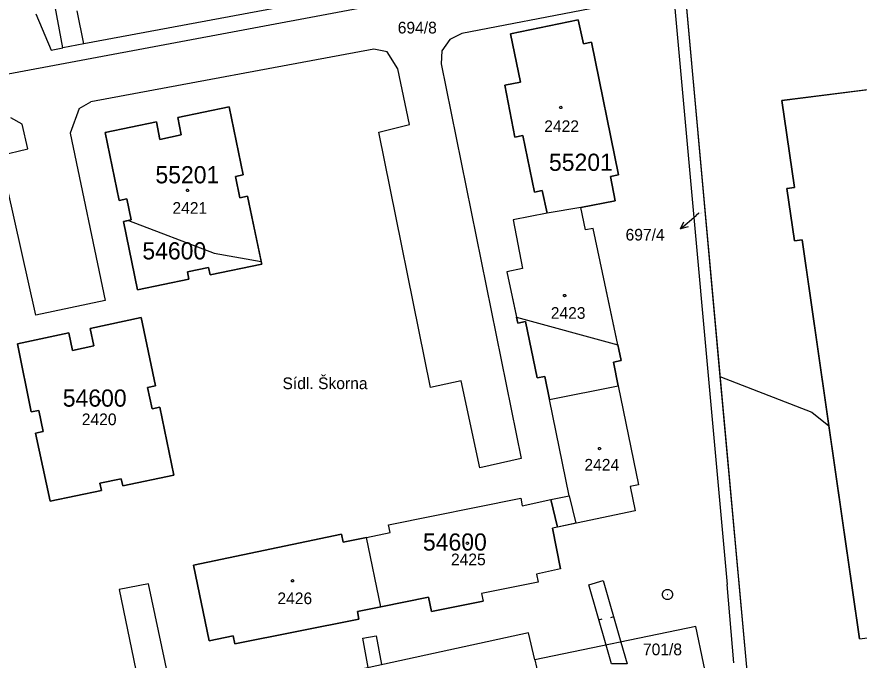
# Model space of a CAD drawing. Extents: x -777309 to -774195, y -1144706 to -1143600.
# Drawn here: x -775028.7 to -774906.1, y -1144612.1 to -1144518.5 of the extents above; entities that cross this region are included whole.
import ezdxf

# ---------------------------------------------------------------- set-up
doc = ezdxf.new("R2010")
doc.units = 0
for name, color, linetype in [('1', 7, 'Continuous'), ('11', 7, 'Continuous'), ('12', 7, 'Continuous'), ('13', 7, 'Continuous'), ('2', 7, 'Continuous'), ('5', 7, 'Continuous'), ('7', 7, 'Continuous'), ('8', 7, 'Continuous')]:
    doc.layers.add(name, color=color, linetype=linetype)

msp = doc.modelspace()

# ---------------------------------------------------------------- linework, layer by layer
at = {"layer": '1'}
for p, q in [((-774936.18, -1144481.83), (-774925.33, -1144601.09)), ((-775022.07, -1144523.02), (-775026.8, -1144497.32)), ((-774932.82, -1144500), (-774922.58, -1144612.56)), ((-775042.26, -1144529.08), (-774944.46, -1144510.75)), ((-774966.48, -1144512.63), (-775018.98, -1144522.44)), ((-775025.96, -1144518.08), (-775023.75, -1144523.35)), ((-775018.98, -1144522.44), (-775019.94, -1144517.62)), ((-774945.27, -1144517.35), (-774963.95, -1144520.9)), ((-774956.89, -1144520.97), (-774947, -1144518.92)), ((-774947, -1144518.92), (-774946.23, -1144522.42)), ((-774963.95, -1144520.9), (-774965.7, -1144521.8)), ((-774955.41, -1144527.99), (-774956.89, -1144520.97)), ((-774965.7, -1144521.8), (-774966.86, -1144523.45)), ((-774946.23, -1144522.42), (-774945.1, -1144522.18)), ((-774945.1, -1144522.18), (-774941.17, -1144541.48)), ((-775023.75, -1144523.35), (-775022.07, -1144523.02)), ((-775018.98, -1144522.44), (-775022.07, -1144523.02)), ((-774976.76, -1144523.19), (-775017.95, -1144530.88)), ((-774974.85, -1144523.59), (-774976.76, -1144523.19)), ((-774973.29, -1144526.08), (-774974.85, -1144523.59)), ((-774966.86, -1144523.45), (-774966.99, -1144525.35)), ((-774917.36, -1144530.66), (-774863.86, -1144523.96)), ((-774966.99, -1144525.35), (-774955.31, -1144582.77)), ((-774971.56, -1144534.16), (-774973.29, -1144526.08)), ((-774957.72, -1144528.45), (-774955.41, -1144527.99)), ((-774956.22, -1144536), (-774957.72, -1144528.45)), ((-774915.53, -1144543.32), (-774917.36, -1144530.66)), ((-775019.67, -1144531.82), (-775021, -1144535.42)), ((-775019.67, -1144531.82), (-775017.95, -1144530.88)), ((-774997.84, -1144531.6), (-775005.32, -1144533.13)), ((-774995.79, -1144541.5), (-774997.84, -1144531.6)), ((-775027.98, -1144534.13), (-775029.64, -1144533.2)), ((-775005.32, -1144533.13), (-775004.8, -1144535.68)), ((-775027.15, -1144537.72), (-775027.98, -1144534.13)), ((-775008.43, -1144533.77), (-775015.89, -1144535.3)), ((-775007.91, -1144536.32), (-775008.43, -1144533.77)), ((-774976.03, -1144535.26), (-774971.56, -1144534.16)), ((-775021, -1144535.42), (-775015.89, -1144559.74)), ((-775015.89, -1144535.3), (-775013.86, -1144545.2)), ((-775004.8, -1144535.68), (-775007.91, -1144536.32)), ((-774968.53, -1144572.4), (-774976.03, -1144535.26)), ((-774955.08, -1144535.77), (-774956.22, -1144536)), ((-774953.37, -1144543.99), (-774955.08, -1144535.77)), ((-775031.16, -1144538.67), (-775027.15, -1144537.72)), ((-775025.99, -1144561.88), (-775031.16, -1144538.67)), ((-774996.91, -1144541.74), (-774995.79, -1144541.5)), ((-774996.28, -1144544.83), (-774996.91, -1144541.74)), ((-774941.17, -1144541.48), (-774942.3, -1144541.71)), ((-774942.3, -1144541.71), (-774941.62, -1144545.26)), ((-774952.24, -1144543.75), (-774953.37, -1144543.99)), ((-774951.55, -1144547.07), (-774952.24, -1144543.75)), ((-774916.62, -1144543.48), (-774915.53, -1144543.32)), ((-774915.52, -1144551.09), (-774916.62, -1144543.48)), ((-775013.86, -1144545.2), (-775012.74, -1144544.97)), ((-775012.74, -1144544.97), (-775012.1, -1144548.05)), ((-774995.15, -1144544.6), (-774996.28, -1144544.83)), ((-774993.08, -1144554.5), (-774995.15, -1144544.6)), ((-774941.62, -1144545.26), (-774946.62, -1144546.23)), ((-774946.62, -1144546.23), (-774951.55, -1144547.07)), ((-774945.94, -1144549.5), (-774946.62, -1144546.23)), ((-774951.55, -1144547.07), (-774956.48, -1144548.05)), ((-775012.1, -1144548.05), (-775013.23, -1144548.28)), ((-775013.23, -1144548.28), (-775011.19, -1144558.19)), ((-774956.48, -1144548.05), (-774955.12, -1144555.1)), ((-774944.82, -1144549.27), (-774945.94, -1144549.5)), ((-774940.75, -1144568.51), (-774944.82, -1144549.27)), ((-774914.43, -1144550.93), (-774915.52, -1144551.09)), ((-774906.05, -1144608.98), (-774914.43, -1144550.93)), ((-775003.91, -1144555.58), (-775000.82, -1144554.95)), ((-775000.82, -1144554.95), (-775000.6, -1144556.03)), ((-775000.6, -1144556.03), (-774993.08, -1144554.5)), ((-774955.12, -1144555.1), (-774957.41, -1144555.59)), ((-775003.69, -1144556.66), (-775003.91, -1144555.58)), ((-774957.41, -1144555.59), (-774955.81, -1144563.06)), ((-775011.19, -1144558.19), (-775003.69, -1144556.66)), ((-775015.89, -1144559.74), (-775025.99, -1144561.88)), ((-775010.63, -1144562.26), (-775018.09, -1144563.83)), ((-775008.57, -1144572.18), (-775010.63, -1144562.26)), ((-775018.09, -1144563.83), (-775017.55, -1144566.37)), ((-774955.81, -1144563.06), (-774954.68, -1144562.82)), ((-774954.68, -1144562.82), (-774953, -1144571.03)), ((-775021.17, -1144564.48), (-775028.63, -1144566.06)), ((-775020.64, -1144567.02), (-775021.17, -1144564.48)), ((-775028.63, -1144566.06), (-775026.65, -1144575.98)), ((-775017.55, -1144566.37), (-775020.64, -1144567.02)), ((-774941.87, -1144568.75), (-774940.75, -1144568.51)), ((-774941.18, -1144572.17), (-774941.87, -1144568.75)), ((-774953, -1144571.03), (-774951.87, -1144570.8)), ((-774951.87, -1144570.8), (-774951.18, -1144574.18)), ((-775009.7, -1144572.42), (-775008.57, -1144572.18)), ((-775009.06, -1144575.52), (-775009.7, -1144572.42)), ((-774964.04, -1144571.46), (-774968.53, -1144572.4)), ((-774961.35, -1144584.12), (-774964.04, -1144571.46)), ((-774951.18, -1144574.18), (-774941.18, -1144572.17)), ((-774941.18, -1144572.17), (-774938.26, -1144586.58)), ((-774948.33, -1144588.17), (-774951.18, -1144574.18)), ((-775026.65, -1144575.98), (-775025.53, -1144575.76)), ((-775025.53, -1144575.76), (-775024.92, -1144578.83)), ((-775007.93, -1144575.29), (-775009.06, -1144575.52)), ((-775005.88, -1144585.19), (-775007.93, -1144575.29)), ((-775024.92, -1144578.83), (-775026.04, -1144579.07)), ((-775026.04, -1144579.07), (-775023.9, -1144588.95)), ((-774955.31, -1144582.77), (-774961.35, -1144584.12)), ((-775016.66, -1144586.34), (-775013.55, -1144585.69)), ((-775013.55, -1144585.69), (-775013.33, -1144586.75)), ((-775013.33, -1144586.75), (-775005.88, -1144585.19)), ((-775016.44, -1144587.4), (-775016.66, -1144586.34)), ((-774938.26, -1144586.58), (-774939.45, -1144586.84)), ((-774939.45, -1144586.84), (-774938.71, -1144590.35)), ((-775023.9, -1144588.95), (-775016.44, -1144587.4)), ((-774951, -1144588.72), (-774948.33, -1144588.17)), ((-774974.64, -1144592.38), (-774955.39, -1144588.5)), ((-774955.39, -1144588.5), (-774955.16, -1144589.62)), ((-774955.16, -1144589.62), (-774951, -1144588.72)), ((-774951, -1144588.72), (-774950.02, -1144592.74)), ((-774938.71, -1144590.35), (-774950.02, -1144592.74)), ((-774974.41, -1144593.52), (-774974.64, -1144592.38)), ((-774950.02, -1144592.74), (-774950.76, -1144592.9)), ((-774949.58, -1144598.79), (-774950.76, -1144592.9)), ((-774981.46, -1144593.78), (-775003.02, -1144598.27)), ((-774981.23, -1144594.91), (-774981.46, -1144593.78)), ((-774977.82, -1144594.22), (-774981.23, -1144594.91)), ((-774977.82, -1144594.22), (-774974.41, -1144593.52)), ((-774975.76, -1144604.34), (-774977.82, -1144594.22)), ((-775003.02, -1144598.27), (-775000.75, -1144609.29)), ((-774949.58, -1144598.79), (-774953.08, -1144599.6)), ((-774953.08, -1144599.6), (-774952.85, -1144600.73)), ((-775009.6, -1144600.96), (-775013.87, -1144601.8)), ((-775013.87, -1144601.8), (-775011.04, -1144615.41)), ((-775006.67, -1144614.66), (-775009.6, -1144600.96)), ((-774952.85, -1144600.73), (-774961.08, -1144602.37)), ((-774924.38, -1144612.47), (-774925.33, -1144601.09)), ((-774975.76, -1144604.34), (-774968.83, -1144602.94)), ((-774968.83, -1144602.94), (-774968.37, -1144605.03)), ((-774961.08, -1144602.37), (-774960.85, -1144603.5)), ((-774979.16, -1144605.01), (-774975.76, -1144604.34)), ((-774968.37, -1144605.03), (-774960.85, -1144603.5)), ((-774978.94, -1144606.14), (-774979.16, -1144605.01)), ((-774996.99, -1144609.71), (-774978.94, -1144606.14)), ((-774929.9, -1144607.21), (-774953.35, -1144612.05)), ((-774928.78, -1144612.51), (-774929.9, -1144607.21)), ((-775000.75, -1144609.29), (-774997.23, -1144608.54)), ((-774954.26, -1144608.09), (-774999.95, -1144618.02)), ((-774997.23, -1144608.54), (-774996.99, -1144609.71)), ((-774953.35, -1144612.05), (-774954.26, -1144608.09)), ((-774953.35, -1144612.05), (-774952.86, -1144614.17))]:
    msp.add_line(p, q, dxfattribs=at)
at = {"layer": '11'}
msp.add_line((-774955.99, -1144562.21), (-774941.23, -1144566.22), dxfattribs=at)
for points in [[(-774873.42, -1144621.66), (-774848.58, -1144616.52), (-774846.04, -1144615.37), (-774842.25, -1144608.21), (-774838.41, -1144597.12), (-774836.58, -1144588.82), (-774837.33, -1144580.31), (-774848.12, -1144528.64), (-774861.71, -1144492.14), (-774875.06, -1144456.94), (-774934.36, -1144461.03), (-774936.34, -1144461.16), (-774935.34, -1144472.21), (-774932.82, -1144500), (-774926.38, -1144570.8)], [(-774941.23, -1144566.22), (-774944.82, -1144549.27), (-774945.94, -1144549.5), (-774946.62, -1144546.23), (-774941.62, -1144545.26), (-774942.3, -1144541.71), (-774941.17, -1144541.48), (-774945.1, -1144522.18), (-774946.23, -1144522.42), (-774947, -1144518.92), (-774956.89, -1144520.97), (-774955.41, -1144527.99), (-774957.72, -1144528.45), (-774956.22, -1144536), (-774955.08, -1144535.77), (-774953.37, -1144543.99), (-774952.24, -1144543.75), (-774951.55, -1144547.07), (-774956.48, -1144548.05), (-774955.12, -1144555.1), (-774957.41, -1144555.59), (-774955.99, -1144562.21)], [(-774884.02, -1144606.24), (-774843.19, -1144601.16), (-774842.67, -1144589.86), (-774851.37, -1144522.52), (-774857.78, -1144523.2), (-774863.86, -1144523.96), (-774917.36, -1144530.66), (-774915.53, -1144543.32), (-774916.62, -1144543.48), (-774915.52, -1144551.09), (-774914.43, -1144550.93), (-774910.52, -1144578.01)], [(-775012.48, -1144548.13), (-775012.1, -1144548.05), (-775012.74, -1144544.97), (-775013.86, -1144545.2), (-775015.89, -1144535.3), (-775008.43, -1144533.77), (-775007.91, -1144536.32), (-775004.8, -1144535.68), (-775005.32, -1144533.13), (-774997.84, -1144531.6), (-774995.79, -1144541.5), (-774996.91, -1144541.74), (-774996.28, -1144544.83), (-774995.15, -1144544.6), (-774993.16, -1144554.11)], [(-774993.16, -1144554.11), (-774993.08, -1144554.5), (-775000.6, -1144556.03), (-775000.82, -1144554.95), (-775003.91, -1144555.58), (-775003.69, -1144556.66), (-775011.19, -1144558.19), (-775013.23, -1144548.28), (-775012.48, -1144548.13)], [(-775012.48, -1144548.13), (-775000, -1144552.89), (-774993.16, -1144554.11)], [(-774941.23, -1144566.22), (-774940.75, -1144568.51), (-774941.87, -1144568.75), (-774941.18, -1144572.17), (-774938.26, -1144586.58), (-774939.45, -1144586.84), (-774938.71, -1144590.35), (-774950.02, -1144592.74), (-774950.76, -1144592.9), (-774949.58, -1144598.79), (-774953.08, -1144599.6), (-774952.85, -1144600.73), (-774961.08, -1144602.37), (-774960.85, -1144603.5), (-774968.37, -1144605.03), (-774968.83, -1144602.94), (-774975.76, -1144604.34), (-774979.16, -1144605.01), (-774978.94, -1144606.14), (-774996.99, -1144609.71), (-774997.23, -1144608.54), (-775000.75, -1144609.29), (-775003.02, -1144598.27), (-774981.46, -1144593.78), (-774981.23, -1144594.91), (-774977.82, -1144594.22), (-774974.41, -1144593.52), (-774974.64, -1144592.38), (-774955.39, -1144588.5), (-774955.16, -1144589.62), (-774951, -1144588.72), (-774948.33, -1144588.17), (-774951.18, -1144574.18), (-774951.87, -1144570.8), (-774953, -1144571.03), (-774954.68, -1144562.82), (-774955.81, -1144563.06), (-774955.99, -1144562.21)], [(-774926.38, -1144570.8), (-774913, -1144576), (-774910.52, -1144578.01)], [(-774926.38, -1144570.8), (-774922.58, -1144612.56), (-774920.86, -1144631.47), (-774889.67, -1144625.02), (-774873.42, -1144621.66)], [(-774910.52, -1144578.01), (-774906.05, -1144608.98), (-774884.02, -1144606.24)], [(-774901, -1144684.4), (-774908.35, -1144649.03), (-774909.67, -1144645.42), (-774911.03, -1144642.74), (-774912.97, -1144640.51), (-774916.07, -1144638.06), (-774918.73, -1144636.66), (-774920.42, -1144636.32), (-774921.69, -1144636.06), (-774922.39, -1144636.1), (-774923.79, -1144636.05), (-774928.78, -1144612.51), (-774929.9, -1144607.21), (-774953.35, -1144612.05), (-774952.86, -1144614.17), (-775047.76, -1144634.76), (-775059.8, -1144637.37), (-775064.48, -1144642.88), (-775074.81, -1144649.2), (-775078.24, -1144651.43), (-775082.04, -1144653.3), (-775086, -1144654.83), (-775089.48, -1144655.85), (-775098.79, -1144659.85)]]:
    msp.add_lwpolyline(points, dxfattribs=at)
msp.add_lwpolyline([(-775021.17, -1144564.48), (-775020.64, -1144567.02), (-775017.55, -1144566.37), (-775018.09, -1144563.83), (-775010.63, -1144562.26), (-775008.57, -1144572.18), (-775009.7, -1144572.42), (-775009.06, -1144575.52), (-775007.93, -1144575.29), (-775005.88, -1144585.19), (-775013.33, -1144586.75), (-775013.55, -1144585.69), (-775016.66, -1144586.34), (-775016.44, -1144587.4), (-775023.9, -1144588.95), (-775026.04, -1144579.07), (-775024.92, -1144578.83), (-775025.53, -1144575.76), (-775026.65, -1144575.98), (-775028.63, -1144566.06)], close=True, dxfattribs=at)
at = {"layer": '12'}
for p, q in [((-774956.89, -1144520.97), (-774947, -1144518.92)), ((-774947, -1144518.92), (-774946.23, -1144522.42)), ((-774955.41, -1144527.99), (-774956.89, -1144520.97)), ((-774946.23, -1144522.42), (-774945.1, -1144522.18)), ((-774945.1, -1144522.18), (-774941.17, -1144541.48)), ((-774957.72, -1144528.45), (-774955.41, -1144527.99)), ((-774956.22, -1144536), (-774957.72, -1144528.45)), ((-774997.84, -1144531.6), (-775005.32, -1144533.13)), ((-774995.79, -1144541.5), (-774997.84, -1144531.6)), ((-775005.32, -1144533.13), (-775004.8, -1144535.68)), ((-775008.43, -1144533.77), (-775015.89, -1144535.3)), ((-775007.91, -1144536.32), (-775008.43, -1144533.77)), ((-775015.89, -1144535.3), (-775013.86, -1144545.2)), ((-775004.8, -1144535.68), (-775007.91, -1144536.32)), ((-774955.08, -1144535.77), (-774956.22, -1144536)), ((-774953.37, -1144543.99), (-774955.08, -1144535.77)), ((-774996.91, -1144541.74), (-774995.79, -1144541.5)), ((-774996.28, -1144544.83), (-774996.91, -1144541.74)), ((-774941.17, -1144541.48), (-774942.3, -1144541.71)), ((-774942.3, -1144541.71), (-774941.62, -1144545.26)), ((-774952.24, -1144543.75), (-774953.37, -1144543.99)), ((-774951.55, -1144547.07), (-774952.24, -1144543.75)), ((-775013.86, -1144545.2), (-775012.74, -1144544.97)), ((-775012.74, -1144544.97), (-775012.1, -1144548.05)), ((-774995.15, -1144544.6), (-774996.28, -1144544.83)), ((-774993.08, -1144554.5), (-774995.15, -1144544.6)), ((-774941.62, -1144545.26), (-774946.62, -1144546.23)), ((-774946.62, -1144546.23), (-774951.55, -1144547.07)), ((-774946.62, -1144546.23), (-774951.55, -1144547.07)), ((-774945.94, -1144549.5), (-774946.62, -1144546.23)), ((-774951.55, -1144547.07), (-774956.48, -1144548.05)), ((-775012.1, -1144548.05), (-775013.23, -1144548.28)), ((-775013.23, -1144548.28), (-775011.19, -1144558.19)), ((-774956.48, -1144548.05), (-774955.12, -1144555.1)), ((-774944.82, -1144549.27), (-774945.94, -1144549.5)), ((-774940.75, -1144568.51), (-774944.82, -1144549.27)), ((-775003.91, -1144555.58), (-775000.82, -1144554.95)), ((-775000.82, -1144554.95), (-775000.6, -1144556.03)), ((-775000.6, -1144556.03), (-774993.08, -1144554.5)), ((-774955.12, -1144555.1), (-774957.41, -1144555.59)), ((-775003.69, -1144556.66), (-775003.91, -1144555.58)), ((-774957.41, -1144555.59), (-774955.81, -1144563.06)), ((-775011.19, -1144558.19), (-775003.69, -1144556.66)), ((-775010.63, -1144562.26), (-775018.09, -1144563.83)), ((-775008.57, -1144572.18), (-775010.63, -1144562.26)), ((-775018.09, -1144563.83), (-775017.55, -1144566.37)), ((-774955.81, -1144563.06), (-774954.68, -1144562.82)), ((-774954.68, -1144562.82), (-774953, -1144571.03)), ((-775021.17, -1144564.48), (-775028.63, -1144566.06)), ((-775020.64, -1144567.02), (-775021.17, -1144564.48)), ((-775028.63, -1144566.06), (-775026.65, -1144575.98)), ((-775017.55, -1144566.37), (-775020.64, -1144567.02)), ((-774941.87, -1144568.75), (-774940.75, -1144568.51)), ((-774941.18, -1144572.17), (-774941.87, -1144568.75)), ((-774953, -1144571.03), (-774951.87, -1144570.8)), ((-774951.87, -1144570.8), (-774951.18, -1144574.18)), ((-775009.7, -1144572.42), (-775008.57, -1144572.18)), ((-775009.06, -1144575.52), (-775009.7, -1144572.42)), ((-774951.18, -1144574.18), (-774941.18, -1144572.17)), ((-774951.18, -1144574.18), (-774941.18, -1144572.17)), ((-774941.18, -1144572.17), (-774938.26, -1144586.58)), ((-774948.33, -1144588.17), (-774951.18, -1144574.18)), ((-775026.65, -1144575.98), (-775025.53, -1144575.76)), ((-775025.53, -1144575.76), (-775024.92, -1144578.83)), ((-775007.93, -1144575.29), (-775009.06, -1144575.52)), ((-775005.88, -1144585.19), (-775007.93, -1144575.29)), ((-775024.92, -1144578.83), (-775026.04, -1144579.07)), ((-775026.04, -1144579.07), (-775023.9, -1144588.95)), ((-775016.66, -1144586.34), (-775013.55, -1144585.69)), ((-775013.55, -1144585.69), (-775013.33, -1144586.75)), ((-775013.33, -1144586.75), (-775005.88, -1144585.19)), ((-775016.44, -1144587.4), (-775016.66, -1144586.34)), ((-774938.26, -1144586.58), (-774939.45, -1144586.84)), ((-774939.45, -1144586.84), (-774938.71, -1144590.35)), ((-775023.9, -1144588.95), (-775016.44, -1144587.4)), ((-774951, -1144588.72), (-774948.33, -1144588.17)), ((-774974.64, -1144592.38), (-774955.39, -1144588.5)), ((-774955.39, -1144588.5), (-774955.16, -1144589.62)), ((-774955.16, -1144589.62), (-774951, -1144588.72)), ((-774951, -1144588.72), (-774950.02, -1144592.74)), ((-774951, -1144588.72), (-774950.02, -1144592.74)), ((-774938.71, -1144590.35), (-774950.02, -1144592.74)), ((-774974.41, -1144593.52), (-774974.64, -1144592.38)), ((-774950.02, -1144592.74), (-774950.76, -1144592.9)), ((-774949.58, -1144598.79), (-774950.76, -1144592.9)), ((-774981.46, -1144593.78), (-775003.02, -1144598.27)), ((-774981.23, -1144594.91), (-774981.46, -1144593.78)), ((-774977.82, -1144594.22), (-774981.23, -1144594.91)), ((-774977.82, -1144594.22), (-774974.41, -1144593.52)), ((-774975.76, -1144604.34), (-774977.82, -1144594.22)), ((-774975.76, -1144604.34), (-774977.82, -1144594.22)), ((-775003.02, -1144598.27), (-775000.75, -1144609.29)), ((-774949.58, -1144598.79), (-774953.08, -1144599.6)), ((-774953.08, -1144599.6), (-774952.85, -1144600.73)), ((-774952.85, -1144600.73), (-774961.08, -1144602.37)), ((-774975.76, -1144604.34), (-774968.83, -1144602.94)), ((-774968.83, -1144602.94), (-774968.37, -1144605.03)), ((-774961.08, -1144602.37), (-774960.85, -1144603.5)), ((-774979.16, -1144605.01), (-774975.76, -1144604.34)), ((-774968.37, -1144605.03), (-774960.85, -1144603.5)), ((-774978.94, -1144606.14), (-774979.16, -1144605.01)), ((-774996.99, -1144609.71), (-774978.94, -1144606.14)), ((-775000.75, -1144609.29), (-774997.23, -1144608.54)), ((-774997.23, -1144608.54), (-774996.99, -1144609.71))]:
    msp.add_line(p, q, dxfattribs=at)
at = {"layer": '13'}
for p, q in [((-774951, -1144588.72), (-774948.33, -1144588.17)), ((-774948.33, -1144588.17), (-774947.38, -1144592.18)), ((-774950.02, -1144592.74), (-774951, -1144588.72)), ((-774947.38, -1144592.18), (-774950.02, -1144592.74)), ((-774943.99, -1144606.22), (-774943.51, -1144606.08)), ((-774941.85, -1144605.8), (-774942.33, -1144605.94)), ((-774978.38, -1144608.9), (-774976.41, -1144608.54)), ((-774977.61, -1144613.16), (-774978.38, -1144608.9)), ((-774976.41, -1144608.54), (-774975.65, -1144612.74))]:
    msp.add_line(p, q, dxfattribs=at)
msp.add_lwpolyline([(-774943.36, -1144600.51), (-774940.8, -1144609.46), (-774939.91, -1144612.61), (-774942.16, -1144612.63), (-774942.94, -1144609.9), (-774945.45, -1144601.11)], close=True, dxfattribs=at)
at = {"layer": '5'}
for points in [[(-774949.56, -1144531.51), (-774949.46, -1144531.53), (-774949.41, -1144531.62), (-774949.39, -1144531.68), (-774949.41, -1144531.77), (-774949.49, -1144531.84), (-774949.56, -1144531.85), (-774949.65, -1144531.82), (-774949.71, -1144531.76), (-774949.73, -1144531.68), (-774949.71, -1144531.59), (-774949.63, -1144531.52)], [(-775003.88, -1144543.58), (-775003.78, -1144543.6), (-775003.73, -1144543.69), (-775003.71, -1144543.75), (-775003.73, -1144543.84), (-775003.81, -1144543.91), (-775003.88, -1144543.92), (-775003.97, -1144543.89), (-775004.03, -1144543.83), (-775004.05, -1144543.75), (-775004.03, -1144543.66), (-775003.95, -1144543.59)], [(-774948.99, -1144558.87), (-774948.89, -1144558.89), (-774948.84, -1144558.98), (-774948.82, -1144559.04), (-774948.84, -1144559.13), (-774948.92, -1144559.2), (-774948.99, -1144559.21), (-774949.08, -1144559.18), (-774949.14, -1144559.12), (-774949.16, -1144559.04), (-774949.14, -1144558.95), (-774949.06, -1144558.88)], [(-775016.7, -1144574.15), (-775016.6, -1144574.17), (-775016.55, -1144574.26), (-775016.53, -1144574.32), (-775016.55, -1144574.41), (-775016.63, -1144574.48), (-775016.7, -1144574.49), (-775016.79, -1144574.46), (-775016.85, -1144574.4), (-775016.87, -1144574.32), (-775016.85, -1144574.23), (-775016.77, -1144574.16)], [(-774943.9, -1144581.13), (-774943.8, -1144581.15), (-774943.75, -1144581.24), (-774943.73, -1144581.3), (-774943.75, -1144581.39), (-774943.83, -1144581.46), (-774943.9, -1144581.47), (-774943.99, -1144581.44), (-774944.05, -1144581.38), (-774944.07, -1144581.3), (-774944.05, -1144581.21), (-774943.97, -1144581.14)], [(-774963.14, -1144594.9), (-774963.04, -1144594.92), (-774962.99, -1144595.01), (-774962.97, -1144595.07), (-774962.99, -1144595.16), (-774963.07, -1144595.23), (-774963.14, -1144595.24), (-774963.23, -1144595.21), (-774963.29, -1144595.15), (-774963.31, -1144595.07), (-774963.29, -1144594.98), (-774963.21, -1144594.91)], [(-774988.6, -1144600.37), (-774988.5, -1144600.39), (-774988.45, -1144600.48), (-774988.43, -1144600.54), (-774988.45, -1144600.63), (-774988.53, -1144600.7), (-774988.6, -1144600.71), (-774988.69, -1144600.68), (-774988.75, -1144600.62), (-774988.77, -1144600.54), (-774988.75, -1144600.45), (-774988.67, -1144600.38)]]:
    msp.add_lwpolyline(points, close=True, dxfattribs=at)
at = {"layer": '7'}
for p in [(-774932.1, -1144549.34), (-774929.46, -1144547.08)]:
    msp.add_line(p, (-774929.82, -1144547.39), dxfattribs=at)
msp.add_lwpolyline([(-774931.01, -1144549.07), (-774932.1, -1144549.34), (-774931.66, -1144548.31)], dxfattribs=at)
at = {"layer": '8'}
msp.add_line((-774934.08, -1144602.52), (-774933.98, -1144602.52), dxfattribs=at)
msp.add_lwpolyline([(-774933.84, -1144601.8), (-774933.5, -1144601.99), (-774933.31, -1144602.33), (-774933.31, -1144602.72), (-774933.5, -1144603.06), (-774933.84, -1144603.25), (-774934.23, -1144603.25), (-774934.57, -1144603.06), (-774934.76, -1144602.72), (-774934.76, -1144602.33), (-774934.57, -1144601.99), (-774934.23, -1144601.8)], close=True, dxfattribs=at)

# ---------------------------------------------------------------- texts
at = {"layer": '11'}
for s, p in [('55201', (-774951.27, -1144540.9)), ('55201', (-775008.57, -1144542.72)), ('54600', (-775010.47, -1144553.79)), ('54600', (-775022.06, -1144575.21)), ('54600', (-774969.62, -1144596.15))]:
    msp.add_text(s, height=2.5, dxfattribs=at).set_placement(p)
at = {"layer": '2'}
for s, height, p in [('694/8', 1.7, (-774973.29, -1144520.92)), ('2422', 1.7, (-774951.96, -1144535.26)), ('2421', 1.7, (-775006.09, -1144547.15)), ('697/4', 0.1, (-774929.44, -1144547.08)), ('2423', 1.7, (-774951.01, -1144562.43)), ('2420', 1.7, (-775019.29, -1144577.9)), ('2424', 1.7, (-774946.11, -1144584.51)), ('2425', 1.7, (-774965.54, -1144598.28)), ('2426', 1.7, (-774990.81, -1144603.94)), ('701/8', 1.7, (-774937.59, -1144611.37))]:
    msp.add_text(s, height=height, dxfattribs=at).set_placement(p)
at = {"layer": '7'}
for s, p in [('697/4', (-774940.12, -1144551.04)), ('Sídl. Škorna', (-774990.07, -1144572.66))]:
    msp.add_text(s, height=1.7, dxfattribs=at).set_placement(p)

doc.saveas('drawing.dxf')
